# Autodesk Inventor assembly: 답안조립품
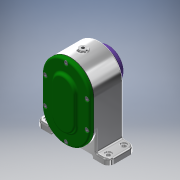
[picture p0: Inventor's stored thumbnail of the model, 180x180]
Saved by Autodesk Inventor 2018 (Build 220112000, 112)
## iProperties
Created: 2021-05
Part Number: 답안조립품
Material: 일반
Document SubType Name: Assembly
Designer: admin
Author: admin
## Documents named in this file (19)
- C:\Users\admin\Desktop\710509V1004\답안조립품.iam
- C:\Users\admin\Desktop\710509V1004\본체.ipt
- C:\Users\admin\Desktop\710509V1004\710509V1004\축 A.ipt
- C:\Users\admin\Desktop\710509V1004\710509V1004\베어링 6002.ipt
- 베어링 6002.ipt
- C:\Users\admin\Desktop\710509V1004\710509V1004\베어링 6001.ipt
- 베어링 6001.ipt
- C:\Users\admin\Desktop\710509V1004\710509V1004\칼라.ipt
- C:\Users\admin\Desktop\710509V1004\710509V1004\키 5 x 5 x 12.ipt
- C:\Users\admin\Desktop\710509V1004\710509V1004\스퍼기어 A.ipt
- C:\Users\admin\Desktop\710509V1004\710509V1004\축 B.ipt
- C:\Users\admin\Desktop\710509V1004\710509V1004\키 4 x 4 x 12.ipt
- C:\Users\admin\Desktop\710509V1004\710509V1004\스퍼기어 B.ipt
- C:\Users\admin\Desktop\710509V1004\710509V1004\개스킷 A.ipt
- C:\Users\admin\Desktop\710509V1004\710509V1004\개스킷 B.ipt
- C:\Users\admin\Desktop\710509V1004\710509V1004\커버 A.ipt
- C:\Users\admin\Desktop\710509V1004\710509V1004\커버 B.ipt
- C:\Users\admin\Desktop\710509V1004\710509V1004\오일 실 12 22 7.ipt
- C:\Users\admin\Desktop\710509V1004\710509V1004\볼트 M4.ipt
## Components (2 placed, 2 different names)
1. 개스킷 A:1
2. 개스킷 B:1
